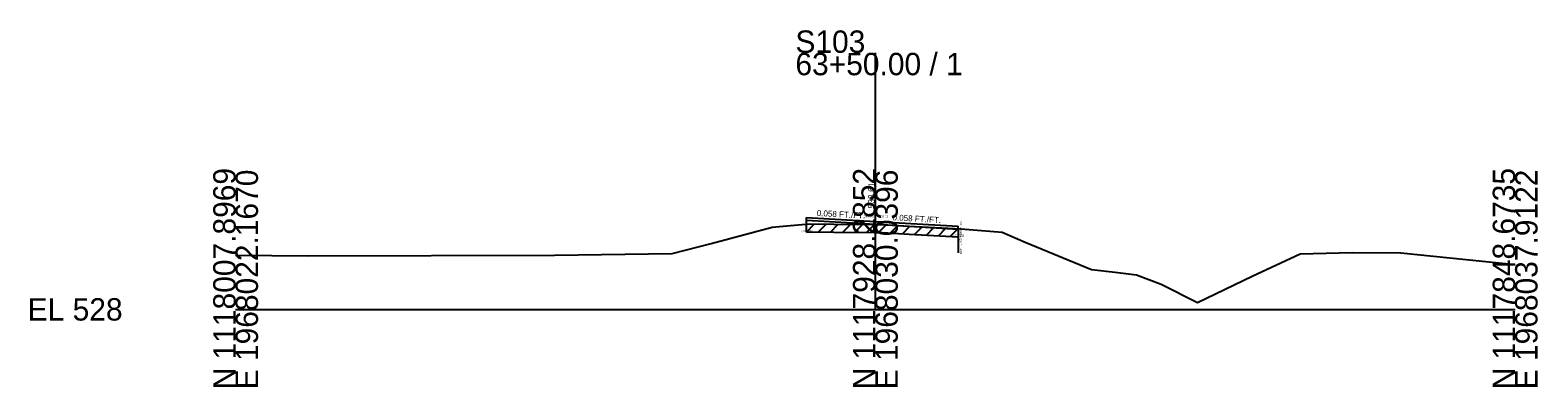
# Model space of a CAD drawing. Extents: x -26 to 163, y -10 to 24018.
# Drawn here: x -25.7 to 162.8, y 11490.3 to 11534.9 of the extents above; entities that cross this region are included whole.
import ezdxf

# ---------------------------------------------------------------- set-up
doc = ezdxf.new("R2010")
doc.units = 0
for name, color, linetype in [('RD_GPK_XS_Cell', 7, 'Continuous'), ('RD_XS_ExGround', 7, 'Continuous'), ('RD_XS_ExPaveRet', 7, 'Continuous'), ('RD_XS_Misc_Line', 7, 'Continuous'), ('RD_XS_PaveOvlay_CP', 7, 'Continuous'), ('RD_XS_TX_Elev_EX', 7, 'Continuous'), ('RD_XS_TX_ExEOP', 7, 'Continuous'), ('RD_XS_TX_Notes', 7, 'Continuous'), ('RD_XS_TX_Profile', 7, 'Continuous'), ('RD_XS_TX_Slope', 7, 'Continuous')]:
    doc.layers.add(name, color=color, linetype=linetype)

msp = doc.modelspace()

# ---------------------------------------------------------------- linework, layer by layer
at = {"layer": 'RD_GPK_XS_Cell'}
for p, q in [((80, 11500), (80, 11532.09)), ((0, 11500), (80, 11500)), ((80, 11500), (160, 11500))]:
    msp.add_line(p, q, dxfattribs=at)
at = {"layer": 'RD_XS_ExGround'}
msp.add_lwpolyline([(0, 11506.78), (9.07, 11506.7), (39.87, 11506.77), (54.6, 11507), (59.47, 11508.26), (67.08, 11510.3), (68.91, 11510.44), (71.77, 11510.7), (74.8, 11510.64), (80, 11510.61), (80.9, 11510.6), (84.21, 11510.4), (90.69, 11510.08), (94.33, 11509.77), (95.85, 11509.66), (98.75, 11508.41), (107.04, 11504.99), (109.97, 11504.64), (112.64, 11504.32), (115.73, 11503.17), (120.27, 11500.88), (127.1, 11504.16), (133.1, 11506.96), (139.62, 11507.1), (145.7, 11507.06), (160, 11505.6)], dxfattribs=at)
at = {"layer": 'RD_XS_ExPaveRet'}
for p, q in [((71.37, 11509.66), (72.4, 11510.68)), ((71.37, 11509.66), (71.37, 11510.66)), ((72.87, 11509.68), (73.85, 11510.66)), ((74.37, 11509.65), (75.36, 11510.64)), ((75.87, 11509.63), (76.87, 11510.63)), ((77.37, 11509.62), (78.37, 11510.62)), ((78.87, 11509.61), (79.87, 11510.61)), ((80.37, 11509.6), (81.34, 11510.57)), ((81.87, 11509.54), (82.82, 11510.49)), ((83.38, 11509.45), (84.32, 11510.4)), ((84.88, 11509.37), (85.83, 11510.32)), ((86.38, 11509.29), (87.33, 11510.25)), ((87.88, 11509.22), (88.83, 11510.17)), ((89.38, 11509.14), (90.33, 11510.09)), ((90.34, 11510.09), (90.34, 11509.09)), ((71.37, 11509.66), (71.77, 11509.7)), ((71.77, 11509.7), (74.8, 11509.64)), ((74.8, 11509.64), (80, 11509.61)), ((80, 11509.61), (80.9, 11509.6)), ((80.9, 11509.6), (84.21, 11509.4)), ((84.21, 11509.4), (90.34, 11509.09))]:
    msp.add_line(p, q, dxfattribs=at)
at = {"layer": 'RD_XS_Misc_Line'}
msp.add_line((90.34, 11510.09), (90.34, 11507.09), dxfattribs=at)
at = {"layer": 'RD_XS_PaveOvlay_CP'}
for p, q in [((71.37, 11511.51), (80, 11511.01)), ((71.37, 11510.66), (71.37, 11511.51)), ((80, 11510.61), (71.37, 11511.11)), ((80, 11511.01), (90.34, 11510.41)), ((90.34, 11510.01), (80, 11510.61)), ((90.34, 11510.09), (90.34, 11510.41))]:
    msp.add_line(p, q, dxfattribs=at)

# ---------------------------------------------------------------- texts
at = {"layer": 'RD_GPK_XS_Cell'}
for s, p in [('S103', (70, 11532.09)), ('63+50.00 / 1', (70, 11529.29)), ('EL 528', (-26, 11498.6))]:
    msp.add_text(s, height=2.8, dxfattribs=at).set_placement(p)
for s, p in [('N 1118007.8969', (0, 11490)), ('N 1117928.2852', (80, 11490)), ('N 1117848.6735', (160, 11490)), ('E 1968022.1670', (2.8, 11490)), ('E 1968030.0396', (82.8, 11490)), ('E 1968037.9122', (162.8, 11490))]:
    msp.add_text(s, height=2.8, rotation=90, dxfattribs=at).set_placement(p)
at = {"layer": 'RD_XS_TX_Elev_EX'}
msp.add_text('538.61', height=0.8, rotation=90, dxfattribs=at).set_placement((79.9, 11512.61))
at = {"layer": 'RD_XS_TX_ExEOP'}
for s, p in [('EOP-L', (71.32, 11511.51)), ('EOP-R', (90.29, 11510.41))]:
    msp.add_text(s, height=0.1, rotation=270, dxfattribs=at).set_placement(p)
at = {"layer": 'RD_XS_TX_Notes'}
for s, p in [(' dE= 0.85', (70.66, 11509.66)), ('Elev. @CL = 539.01', (78.49, 11511.51)), (' dE= 0.41', (79.3, 11509.61)), (' dE= 0.32', (89.62, 11509.09))]:
    msp.add_text(s, height=0.25, dxfattribs=at).set_placement(p)
msp.add_text(' Min. Distance @CP = -0.09', height=0.25, rotation=270, dxfattribs=at).set_placement((90.59, 11511.19))
at = {"layer": 'RD_XS_TX_Profile'}
msp.add_text('CL', height=0.25, dxfattribs=at).set_placement((79.77, 11511.01))
at = {"layer": 'RD_XS_TX_Slope'}
for p in [(72.65, 11511.69), (82.13, 11511.14)]:
    msp.add_text('0.058 FT./FT.', height=0.75, rotation=356.6806, dxfattribs=at).set_placement(p)

doc.saveas('drawing.dxf')
